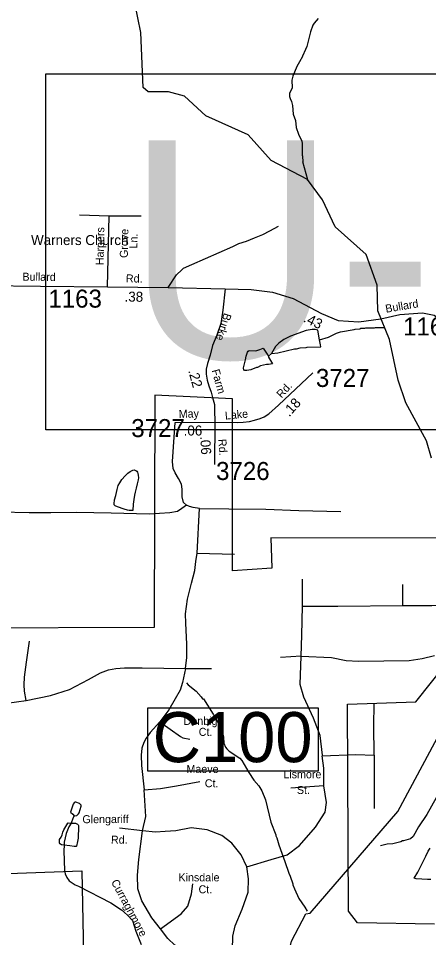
# Model space of a CAD drawing. Extents: x 1551653 to 1702041, y 811336 to 920032.
# Drawn here: x 1581472 to 1584838, y 836233 to 843767 of the extents above; entities that cross this region are included whole.
import ezdxf

# ---------------------------------------------------------------- set-up
doc = ezdxf.new("R2010")
doc.units = 0
for name, color, linetype in [('Old_Level_10', 7, 'Continuous'), ('Old_Level_11', 7, 'Continuous'), ('Old_Level_17', 7, 'Continuous'), ('Old_Level_22', 7, 'Continuous'), ('Old_Level_3', 7, 'Continuous'), ('Old_Level_31', 7, 'Continuous'), ('Old_Level_32', 7, 'Continuous'), ('Old_Level_35', 7, 'Continuous'), ('Old_Level_48', 7, 'Continuous'), ('Old_Level_49', 7, 'Continuous'), ('Old_Level_59', 7, 'Continuous'), ('Old_Level_62', 7, 'Continuous'), ('Old_Level_8', 7, 'Continuous')]:
    doc.layers.add(name, color=color, linetype=linetype)

msp = doc.modelspace()

# ---------------------------------------------------------------- linework, layer by layer
at = {"layer": 'Old_Level_3'}
msp.add_lwpolyline([(1588533.951, 840394.567), (1581697.433, 840394.567), (1581697.433, 843313.169), (1588533.951, 843313.169), (1588533.951, 840394.567)], dxfattribs=at)
at = {"layer": 'Old_Level_31'}
msp.add_lwpolyline([(1582533.65, 838116.427), (1583932.243, 838116.427), (1583932.243, 837597.877), (1582533.65, 837597.877), (1582533.65, 838116.427)], dxfattribs=at)
at = {"layer": 'Old_Level_32'}
for p, q in [((1582758.829, 840455.482), (1583083.428, 840459.013)), ((1583083.428, 840459.013), (1583079.899, 840109.504))]:
    msp.add_line(p, q, dxfattribs=at)
for points in [[(1581206.115, 841579.229), (1581654.769, 841572.213), (1582204.736, 841566.495), (1582699.935, 841561.316), (1583168.014, 841551.186)], [(1583168.014, 841551.186), (1583150.464, 841376.915), (1583132.823, 841267.473), (1583101.069, 841172.153), (1583065.787, 841087.423), (1583044.617, 841006.224), (1583023.448, 840939.146), (1583014.164, 840892.232), (1583014.164, 840850.78), (1583020.378, 840803.112), (1583034.033, 840755.566), (1583055.202, 840702.61), (1583065.787, 840660.246), (1583079.899, 840603.759), (1583079.899, 840557.864), (1583083.428, 840459.013)], [(1583168.014, 841551.186), (1583380.776, 841544.239), (1583556.032, 841523.189), (1583727.783, 841470.568), (1583959.121, 841347.784), (1584095.82, 841291.654), (1584264.065, 841281.13), (1584446.332, 841305.687), (1584600.557, 841340.768), (1584786.328, 841354.8), (1584884.471, 841333.751), (1584975.604, 841267.097), (1585101.788, 841193.426), (1585266.529, 841147.821), (1585384.12, 841147.938)], [(1583083.428, 840459.013), (1583273.953, 840455.482), (1583316.293, 840459.013), (1583368.355, 840463.214), (1583408.027, 840473.135), (1583456.724, 840488.466), (1583488.479, 840502.587), (1583527.988, 840526.091), (1583605.61, 840596.699), (1583887.869, 840861.478)]]:
    msp.add_lwpolyline(points, dxfattribs=at)
at = {"layer": 'Old_Level_35'}
for p, q in [((1581973.008, 842158.166), (1582217.363, 842148.025)), ((1582204.736, 841566.495), (1582217.363, 842148.025)), ((1582217.363, 842148.025), (1582480.042, 842149.882)), ((1582937.702, 839384.929), (1582958.926, 839750.358)), ((1582937.702, 839384.929), (1583244.994, 839375.7)), ((1583803.228, 838948.297), (1583803.228, 839170.031)), ((1583793.158, 838540.104), (1583621.963, 838530.025)), ((1582843.575, 838438.135), (1583056.743, 838438.135)), ((1583979.457, 837476.788), (1583707.56, 837456.63)), ((1582490.603, 837107.912), (1582302.315, 837128.85))]:
    msp.add_line(p, q, dxfattribs=at)
for points in [[(1582699.935, 841561.316), (1582769.535, 841666.418), (1582811.933, 841705.719), (1582828.236, 841719.616), (1582894.735, 841750.518), (1583231.034, 841897.716), (1583281.434, 841923.117), (1583343.635, 841942.116), (1583408.034, 841969.216), (1583476.633, 841996.217), (1583535.032, 842025.518), (1583607.634, 842064.415)], [(1582851.881, 839776.197), (1582826.965, 839798.344), (1582815.892, 839844.484), (1582815.892, 839907.234), (1582810.354, 839949.683), (1582786.362, 839995.823), (1582758.678, 840043.808), (1582742.067, 840078.876), (1582736.531, 840134.243), (1582758.829, 840455.482)], [(1582851.881, 839776.197), (1582814.046, 839750.358), (1582777.133, 839726.365), (1582714.383, 839715.291), (1582544.588, 839704.218), (1582232.681, 839711.6), (1581949.381, 839717.137), (1581738.983, 839713.446), (1581560.882, 839715.291), (1581322.799, 839720.828), (1581147.466, 839718.983), (1581025.657, 839720.828)], [(1582958.926, 839750.358), (1582907.249, 839757.74), (1582875.873, 839766.968), (1582851.881, 839776.197)], [(1582958.926, 839750.358), (1583199.777, 839746.667), (1583501.532, 839744.821), (1583771.913, 839733.748), (1584117.964, 839724.519)], [(1582843.575, 838438.135), (1582853.726, 838528.57), (1582853.726, 838637.46), (1582845.421, 838810.946), (1582843.575, 838886.616), (1582861.109, 839006.58), (1582892.484, 839137.618), (1582921.091, 839242.818), (1582928.473, 839314.796), (1582937.702, 839384.929)], [(1584626.131, 838955.637), (1584626.131, 839076.25), (1584626.131, 839127.941)], [(1583793.158, 838540.104), (1583798.193, 838711.445), (1583803.228, 838948.297)], [(1583803.228, 838948.297), (1584094.163, 838948.745), (1584626.131, 838955.637)], [(1584626.131, 838955.637), (1584865.431, 838953.914), (1584941.18, 838957.36)], [(1581536.889, 838176.059), (1581523.047, 838253.574), (1581519.355, 838305.251), (1581523.047, 838368.001), (1581537.812, 838489.811), (1581563.65, 838661.452)], [(1583966.649, 837727.984), (1583949.246, 837890.02), (1583893.86, 838031.124), (1583813.298, 838202.464), (1583783.087, 838308.291), (1583793.158, 838540.104)], [(1583793.158, 838540.104), (1584039.879, 838530.025), (1584160.722, 838504.829), (1584261.425, 838499.789), (1584679.341, 838504.829), (1584785.079, 838519.947), (1584885.782, 838545.144)], [(1581536.889, 838176.059), (1581735.291, 838218.508), (1581892.167, 838266.493), (1582046.275, 838347.7), (1582145.938, 838403.068), (1582212.38, 838427.061), (1582271.439, 838439.98), (1582341.572, 838445.517), (1582488.297, 838445.517), (1582843.575, 838438.135)], [(1582843.575, 838438.135), (1582818.66, 838323.707), (1582798.358, 838260.957), (1582757.755, 838190.824), (1582707.923, 838100.39), (1582633.177, 838002.572)], [(1580514.425, 838067.169), (1580566.102, 838074.551), (1580691.603, 838089.316), (1580826.332, 838111.463), (1580931.531, 838124.382), (1581074.566, 838128.073), (1581224.059, 838137.301), (1581378.167, 838153.911), (1581536.889, 838176.059)], [(1584392.339, 837728.759), (1584387.303, 837970.651), (1584392.339, 838147.03)], [(1582633.177, 838002.572), (1582553.816, 837913.983), (1582520.595, 837867.843), (1582500.293, 837830.931), (1582485.529, 837784.791), (1582479.069, 837729.423), (1582482.76, 837642.68), (1582503.678, 837445.526)], [(1582633.177, 838002.572), (1582801.127, 837882.608), (1582821.428, 837871.534), (1582878.642, 837858.615)], [(1583964.352, 837723.72), (1584241.284, 837733.798), (1584392.339, 837728.759)], [(1583979.457, 837476.788), (1583979.457, 837622.931), (1583964.352, 837723.72)], [(1584392.339, 837728.759), (1584392.339, 837507.025), (1584392.339, 837290.33)], [(1582503.678, 837445.526), (1582639.494, 837454.623), (1582770.249, 837478.177), (1582961.153, 837512.2)], [(1582490.603, 837107.912), (1582516.754, 837225.684), (1582503.678, 837445.526)], [(1583345.727, 836813.496), (1583546.436, 836872.058), (1583677.349, 836912.374), (1583778.052, 836987.965), (1583908.965, 837139.147), (1583989.528, 837260.094), (1583999.598, 837340.724), (1583979.457, 837476.788)], [(1582637.03, 836305.766), (1582566.422, 836394.75), (1582485.353, 836533.459), (1582451.357, 836632.911), (1582448.742, 836745.45), (1582461.818, 836873.691), (1582490.603, 837107.912)], [(1583345.727, 836813.496), (1583298.674, 836911.625), (1583222.836, 837008.46), (1583141.767, 837068.654), (1583021.471, 837115.764), (1582890.716, 837131.467), (1582765.19, 837107.912), (1582676.277, 837102.678), (1582597.823, 837097.444), (1582490.603, 837107.912)], [(1583228.091, 836131.735), (1583230.661, 836245.572), (1583251.582, 836329.321), (1583309.115, 836465.413), (1583356.187, 836606.74), (1583361.417, 836714.044), (1583345.727, 836813.496)], [(1582637.03, 836305.766), (1582807.013, 836428.773), (1582861.93, 836491.585), (1582893.312, 836591.037), (1582903.772, 836674.786)], [(1583228.091, 836131.735), (1583097.29, 836133.034), (1582932.538, 836127.799), (1582841.01, 836140.886), (1582754.711, 836172.291), (1582697.178, 836224.635), (1582637.03, 836305.766)]]:
    msp.add_lwpolyline(points, dxfattribs=at)
at = {"layer": 'Old_Level_48'}
for points in [[(1584930.306, 839508.076), (1583543.585, 839509.214), (1583551.085, 839261.479), (1583228.578, 839238.958), (1583229.742, 840648.769), (1582592.227, 840678.798), (1582584.976, 838774.554), (1581010.522, 838769.336), (1581018.023, 838153.753), (1580529.781, 838154.587), (1580542.047, 837792.436), (1581014.281, 837801.643), (1581014.281, 837482.459), (1580548.18, 837457.906), (1580554.312, 836728.239), (1581993.045, 836779.951), (1582030.773, 834859.596)], [(1584886.841, 836342.85), (1584254.214, 836352.96), (1584179.212, 836450.553), (1584171.695, 838145.207), (1584733.959, 838165.745), (1584988.965, 838488.552)]]:
    msp.add_lwpolyline(points, dxfattribs=at)
at = {"layer": 'Old_Level_49'}
for points in [[(1584930.306, 839508.076), (1583543.585, 839509.214), (1583551.085, 839261.479), (1583228.578, 839238.958), (1583229.742, 840648.769), (1582592.227, 840678.798), (1582584.976, 838774.554), (1581010.522, 838769.336), (1581018.023, 838153.753), (1580529.781, 838154.587), (1580542.047, 837792.436), (1581014.281, 837801.643), (1581014.281, 837482.459), (1580548.18, 837457.906), (1580554.312, 836728.239), (1581993.045, 836779.951), (1582030.773, 834859.596)], [(1584886.841, 836342.85), (1584254.214, 836352.96), (1584179.212, 836450.553), (1584171.695, 838145.207), (1584733.959, 838165.745), (1584988.965, 838488.552)]]:
    msp.add_lwpolyline(points, dxfattribs=at)
at = {"layer": 'Old_Level_59'}
for points in [[(1584861.599, 840162.977), (1584821.511, 840304.925), (1584651.523, 840616.912), (1584587.547, 840802.074), (1584516.496, 841135.078), (1584420.532, 841370.068), (1584415.508, 841580.246), (1584326.515, 841831.538), (1584071.533, 842059.914), (1583966.546, 842278.705), (1583843.515, 842445.361), (1583546.497, 842602.379), (1583357.542, 842813.07), (1583009.568, 842967.782), (1582836.504, 843128.851), (1582703.528, 843164.376), (1582537.538, 843164.479), (1582495.503, 843201.439), (1582477.561, 843651.528), (1582329.513, 844376.747)], [(1583831.52, 836428.415), (1583865.558, 836434.259), (1584585.599, 837266.617), (1585091.565, 838208.318), (1585117.504, 838293.159)], [(1582991.524, 832538.936), (1583025.562, 832577.691), (1583027.51, 832728.661), (1582946.515, 832864.918), (1582956.562, 833005.839), (1583227.817, 833980.619), (1583257.157, 834111.126), (1583361.481, 834168.222), (1583441.355, 834277.522), (1583511.536, 834432.387), (1583602.579, 834962.344), (1583667.58, 836011.493), (1583711.564, 836204.344), (1583831.52, 836428.415)]]:
    msp.add_lwpolyline(points, dxfattribs=at)
at = {"layer": 'Old_Level_62'}
msp.add_line((1583523.121, 840999.282), (1583549.47, 841019.89), dxfattribs=at)
for points in [[(1583930.765, 843767.28), (1583898.366, 843727.705), (1583888.114, 843711.814), (1583867.506, 843656.142), (1583838.081, 843536.546), (1583792.867, 843433.148), (1583788.459, 843430.892), (1583756.163, 843373.632), (1583723.252, 843294.072), (1583714.845, 843262.237), (1583718.126, 843198.21), (1583697.518, 843150.484), (1583697.21, 843126.493), (1583701.004, 843110.448), (1583712.794, 843086.302), (1583720.381, 843054.263), (1583727.558, 842982.188), (1583746.936, 842929.95), (1583750.216, 842873.92), (1583769.594, 842817.736), (1583796.866, 842761.397), (1583800.659, 842741.354), (1583799.531, 842645.44), (1583803.427, 842637.392), (1583805.375, 842592.691)], [(1583838.316, 842448.028), (1583846.313, 842443.927), (1583805.375, 842592.691)], [(1583942.863, 841132.771), (1583928.304, 841211.306), (1583906.569, 841216.74), (1583882.577, 841216.997), (1583834.493, 841209.615), (1583705.925, 841163.273), (1583649.638, 841136.001), (1583609.243, 841106.524), (1583580.946, 841076.894), (1583549.47, 841019.89)], [(1583942.863, 841132.771), (1584017.809, 841155.327), (1584082.093, 841186.546), (1584114.286, 841198.132), (1584226.45, 841216.689), (1584234.549, 841220.585), (1584274.535, 841224.071), (1584282.634, 841227.967), (1584314.622, 841227.557), (1584322.619, 841231.504), (1584394.593, 841230.581), (1584402.59, 841234.477), (1584466.566, 841233.657), (1584478.801, 841227.382)], [(1583549.47, 841019.89), (1583600.323, 841024.658), (1583736.683, 841058.902), (1583752.677, 841058.747), (1583782.82, 841066.334), (1583832.852, 841069.718), (1583840.849, 841073.614), (1583953.115, 841074.331), (1583951.065, 841092.223), (1583942.863, 841132.771)], [(1583523.121, 840999.282), (1583523.941, 840989.645), (1583557.775, 840936.178), (1583523.224, 840929.667), (1583507.23, 840929.872), (1583459.042, 840918.492), (1583434.949, 840906.804), (1583426.952, 840906.906), (1583378.765, 840887.478), (1583346.674, 840879.891), (1583330.68, 840880.096), (1583322.683, 840884.197), (1583318.992, 840904.241), (1583335.704, 840968.012), (1583340.112, 840999.949), (1583352.415, 841031.783), (1583358.567, 841039.678), (1583366.564, 841045.573), (1583420.595, 841042.907), (1583452.686, 841054.493), (1583479.343, 841064.079), (1583484.674, 841056.082), (1583523.121, 840999.282)], [(1582367.038, 839737.751), (1582340.176, 839744.158), (1582284.402, 839762.818), (1582266.357, 839771.943), (1582258.257, 839779.377), (1582256.822, 839788.706), (1582261.538, 839821.361), (1582271.483, 839856.989), (1582278.147, 839881.236), (1582283.684, 839904.509), (1582287.785, 839927.783), (1582291.578, 839938.599), (1582304.394, 839961.719), (1582322.029, 839987.863), (1582349.506, 840019.031), (1582369.601, 840039.946), (1582389.593, 840053.069), (1582411.021, 840064.604), (1582420.966, 840065.988), (1582428.656, 840065.322), (1582435.422, 840062.604), (1582443.112, 840056.248), (1582449.674, 840047.328), (1582453.672, 840037.383), (1582456.03, 840023.849), (1582456.645, 840000.986), (1582455.825, 839984.429), (1582447.52, 839952.901), (1582437.575, 839915.736), (1582429.271, 839885.234), (1582424.145, 839858.885), (1582418.813, 839824.18), (1582414.507, 839785.374), (1582409.996, 839732.522), (1582382.519, 839734.06), (1582367.038, 839737.751)], [(1582852.396, 838321.251), (1582864.186, 838305.103), (1582931.546, 838252.302), (1582972.966, 838205.807), (1582982.809, 838189.71), (1582990.806, 838189.608), (1583071.289, 838064.629), (1583131.984, 837955.899), (1583143.57, 837923.758), (1583155.053, 837875.673), (1583158.436, 837827.639), (1583172.072, 837793.498), (1583181.915, 837779.349), (1583201.702, 837761.151), (1583288.952, 837704.044), (1583306.791, 837685.846), (1583361.54, 837585.217), (1583404.806, 837524.675), (1583444.279, 837476.18), (1583469.808, 837435.887), (1583500.873, 837363.555), (1583542.704, 837179.111), (1583585.457, 837074.637), (1583585.354, 837066.64), (1583593.146, 837050.543), (1583608.525, 836994.359), (1583658.866, 836857.794), (1583689.726, 836761.42), (1583701.414, 836737.326), (1583724.687, 836673.043), (1583724.585, 836665.046), (1583736.17, 836632.903), (1583773.182, 836552.472), (1583822.395, 836483.882), (1583841.772, 836451.022)], [(1585497.978, 837911.455), (1585455.122, 837922.732), (1585423.134, 837927.141), (1585263.193, 837929.14), (1585255.196, 837925.244), (1585223.208, 837923.655), (1585201.062, 837909.917), (1585184.863, 837894.128), (1585142.007, 837822.718), (1585131.755, 837798.829), (1585076.596, 837703.583), (1585043.89, 837640.016), (1584982.682, 837536.824), (1584900.764, 837377.96), (1584823.151, 837242.985), (1584755.997, 837139.844), (1584710.988, 837060.488), (1584688.842, 837042.751), (1584632.658, 837025.475), (1584624.661, 837025.578), (1584608.564, 837017.786), (1584544.383, 837002.561), (1584496.401, 836999.178), (1584442.37, 836986.465)], [(1581929.661, 837231.348), (1581951.705, 837235.09), (1581965.853, 837246.881), (1581972.005, 837256.826), (1581988.614, 837310.6), (1581988.716, 837318.597), (1581974.875, 837332.746), (1581942.99, 837343.153), (1581936.941, 837343.204), (1581928.944, 837337.309), (1581922.792, 837327.415), (1581900.236, 837262.26), (1581919.819, 837245.496), (1581929.661, 837231.348)], [(1581929.661, 837231.348), (1581923.612, 837223.453), (1581908.028, 837178.804), (1581904.338, 837172.293)], [(1581846.718, 836991.283), (1581827.443, 836994.359), (1581817.908, 836997.845), (1581811.346, 837002.407), (1581808.476, 837009.071), (1581808.373, 837022.707), (1581810.834, 837036.343), (1581822.932, 837057.515), (1581830.314, 837075.047), (1581837.696, 837098.166), (1581845.693, 837116.826), (1581868.556, 837157.324), (1581877.681, 837171.934), (1581881.782, 837172.96), (1581904.338, 837172.293)], [(1581904.338, 837172.293), (1581886.088, 837139.997), (1581864.045, 837086.068), (1581848.051, 837014.403), (1581846.718, 836991.283)], [(1581904.338, 837172.293), (1581940.017, 837171.165), (1581947.296, 837169.576), (1581957.549, 837163.475), (1581962.982, 837156.76), (1581965.135, 837151.532), (1581965.34, 837144.15), (1581962.572, 837049.056), (1581958.061, 837021.118), (1581947.809, 836982.209), (1581945.143, 836979.339), (1581930.789, 836978.468), (1581893.265, 836983.952), (1581846.718, 836991.283)], [(1581846.718, 836991.283), (1581844.052, 836943.25), (1581851.024, 836783.053), (1581855.638, 836755.268), (1581869.171, 836724.869), (1581890.291, 836699.392), (1581939.094, 836666.019), (1581966.161, 836653.716), (1582231.088, 836517.869), (1582319.363, 836460.147), (1582368.883, 836415.856), (1582409.381, 836373.717), (1582436.345, 836285.392), (1582478.996, 836176.919)], [(1584855.755, 836710.157), (1584829.303, 836709.695), (1584735.799, 836716.103), (1584717.96, 836719.282), (1584748.102, 836768.802), (1584770.556, 836812.786), (1584791.061, 836852.104), (1584813.616, 836900.804), (1584835.147, 836942.019), (1584849.706, 836966.318)]]:
    msp.add_lwpolyline(points, dxfattribs=at)

# ---------------------------------------------------------------- texts
at = {"layer": 'Old_Level_10'}
for s, height, rotation, p in [('Harpers', 65.6167, 88.7561806, (1582170.795, 841743.322)), ('Grove', 65.6167, 88.7561806, (1582369.794, 841802.984)), ('Ln.', 65.6167, 88.7561806, (1582447.914, 841880.583)), ('Glengariff', 65.6167, 0.2815722, (1581997.931, 837170.503)), ('Rd.', 65.6166, 359.8659361, (1582231.797, 837003.292)), ('Kinsdale', 65.6167, 0.0080222, (1582785.594, 836694.015)), ('Curraghmore', 65.61666, 298.2864167, (1582230.685, 836688.594)), ('Ct.', 65.6166, 359.7227278, (1582950.344, 836596.406))]:
    msp.add_text(s, height=height, rotation=rotation, dxfattribs=at).set_placement(p)
for s, p in [('Denbigh', (1582827.779, 837976.583)), ('Ct.', (1582952.127, 837886.539)), ('Maeve', (1582851.232, 837582.077)), ('Lismore', (1583646.173, 837539.069)), ('Ct.', (1583001.683, 837465.201)), ('St.', (1583757.194, 837410.417))]:
    msp.add_text(s, height=65.6167, dxfattribs=at).set_placement(p)
at = {"layer": 'Old_Level_11'}
for s, rotation, p in [('Bullard', 359.4007722, (1581505.117, 841617.485)), ('Rd.', 359.4008222, (1582354.324, 841603.337)), ('Bullard', 9.6424611, (1584488.664, 841354.438)), ('Burke', 252.7598444, (1583159.673, 841357.088)), ('Farm', 285.5096583, (1583057.176, 840882.059)), ('Rd.', 47.7545222, (1583631.68, 840650.129)), ('May', 2.0475222, (1582788.888, 840491.632)), ('Lake', 5.1996222, (1583169.769, 840478.45)), ('Rd.', 273.6480667, (1583112.436, 840318.038))]:
    msp.add_text(s, height=65.6167, rotation=rotation, dxfattribs=at).set_placement(p)
at = {"layer": 'Old_Level_17'}
for s, rotation, p in [('.38', 359.4008222, (1582343.185, 841446.127)), ('.43', 334.4756361, (1583804.494, 841283.441)), ('.22', 285.5096583, (1582864.802, 840879.447)), ('.18', 47.7545222, (1583693.877, 840497.398)), ('.06', 359.9404583, (1582828.213, 840348.37)), ('.06', 273.6480667, (1582963.618, 840341.03))]:
    msp.add_text(s, height=82.0208, rotation=rotation, dxfattribs=at).set_placement(p)
at = {"layer": 'Old_Level_22'}
msp.add_text('Warners Church', height=82.02083, dxfattribs=at).set_placement((1581576.618, 841909.42))
at = {"layer": 'Old_Level_3'}
msp.add_text('U-3119', height=1788.0542, dxfattribs=at).set_placement((1582356.151, 840980.253))
at = {"layer": 'Old_Level_31'}
msp.add_text('C100', height=410.1042, dxfattribs=at).set_placement((1582574.317, 837671.004))
at = {"layer": 'Old_Level_8'}
for s, p in [('1163', (1581718.464, 841396.489)), ('1163', (1584628.168, 841168.262)), ('3727', (1583913.01, 840746.323)), ('3727', (1582398.31, 840335.451)), ('3726', (1583094.185, 839983.749))]:
    msp.add_text(s, height=147.6375, dxfattribs=at).set_placement(p)

doc.saveas('drawing.dxf')
